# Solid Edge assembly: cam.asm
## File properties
Author: Deepak Maini
Template: Normal.asm
Last saved by: MYPC
Revision: 6
Application: Solid Edge
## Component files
cam.par
floorere.par
follower.par
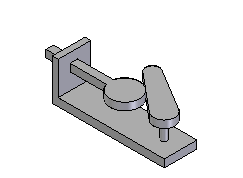
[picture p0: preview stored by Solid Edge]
